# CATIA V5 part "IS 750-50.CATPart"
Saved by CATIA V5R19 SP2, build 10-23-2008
Part number: IS 750-50
Bounding box of the stored display mesh (mm): x -24.865 to 24.865, y -24.997 to 24.997, z 0 to 195
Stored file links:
  C:\Users\Bora\Desktop\3D Katı model\IS serisi\IS 750\IS 750-50.CATPart
  C:\Program Files\Dassault Systemes\B19\intel_a\reffiles\standard\MetricThickPitch.txt
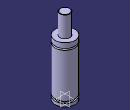
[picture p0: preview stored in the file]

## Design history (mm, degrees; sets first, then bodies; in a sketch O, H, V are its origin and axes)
Body1 (main body)
  Sketch1 on yz-plane, origin (0, 0, 0), H (0, 1, 0), V (0, 0, 1)
    point P1 (25, 129.5)
    point P4 (25, 125.5)
    point P7 (12.5, 194)
    point P9 (12.5, 194)
    point P13 (25, 129.5)
    point P14 (25, 125.5)
    line L1 (25, 129.5) -> (25, 142)
    line L2 (25, 13) -> (25, 125.5)
    line L3 (21.5, 13) -> (21.5, 8)
    arc A1 centre (11.5, 194) radius 1 from (12.5, 194) to (11.5, 195) ccw
    line L4 (12.5, 194) -> (12.5, 142)
    line L5 (25, 0) -> (25, 8)
    arc A2 centre (25, 127.5) radius 2 from (25, 129.5) to (25, 125.5) ccw
    line L6 (11.5, 195) -> (0, 195)
    point P15 (0, 195)
    line L7 (12.5, 142) -> (25, 142)
    line L8 (0, 0) -> (25, 0)
    line L9 (21.5, 8) -> (25, 8)
    line L10 (21.5, 13) -> (25, 13)
    coincidence: P15 V, P1 P13, P4 P14, P7 P9
    tangency: L6 A1
    horizontal: L7 H, L8 H, L9 H
  Shaft1: profile Sketch1, axis Sketch1.V, angle 360
  Sketch2 on face of Shaft1 from Sketch1.L8, origin (0, 0, 0), H (1, 0, 0), V (0, -1, 0)
    point P1 (10, 0)
    distance P1 V = 10
  Hole1: placed by Sketch2, at (10, 0, 0) direction (0, 0, 1), diameter 6.647, depth 13, threaded "M8", thread diameter 8, thread depth 13, pitch 1.25
  Sketch3 on face of Shaft1 from Sketch1.L8, origin (0, 0, 0), H (1, 0, 0), V (0, -1, 0)
    point P1 (-10, 0)
    distance P1 V = 10
  Hole2: placed by Sketch3, at (-10, 0, 0) direction (0, 0, 1), diameter 6.647, depth 13, threaded "M8", thread diameter 8, thread depth 13, pitch 1.25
